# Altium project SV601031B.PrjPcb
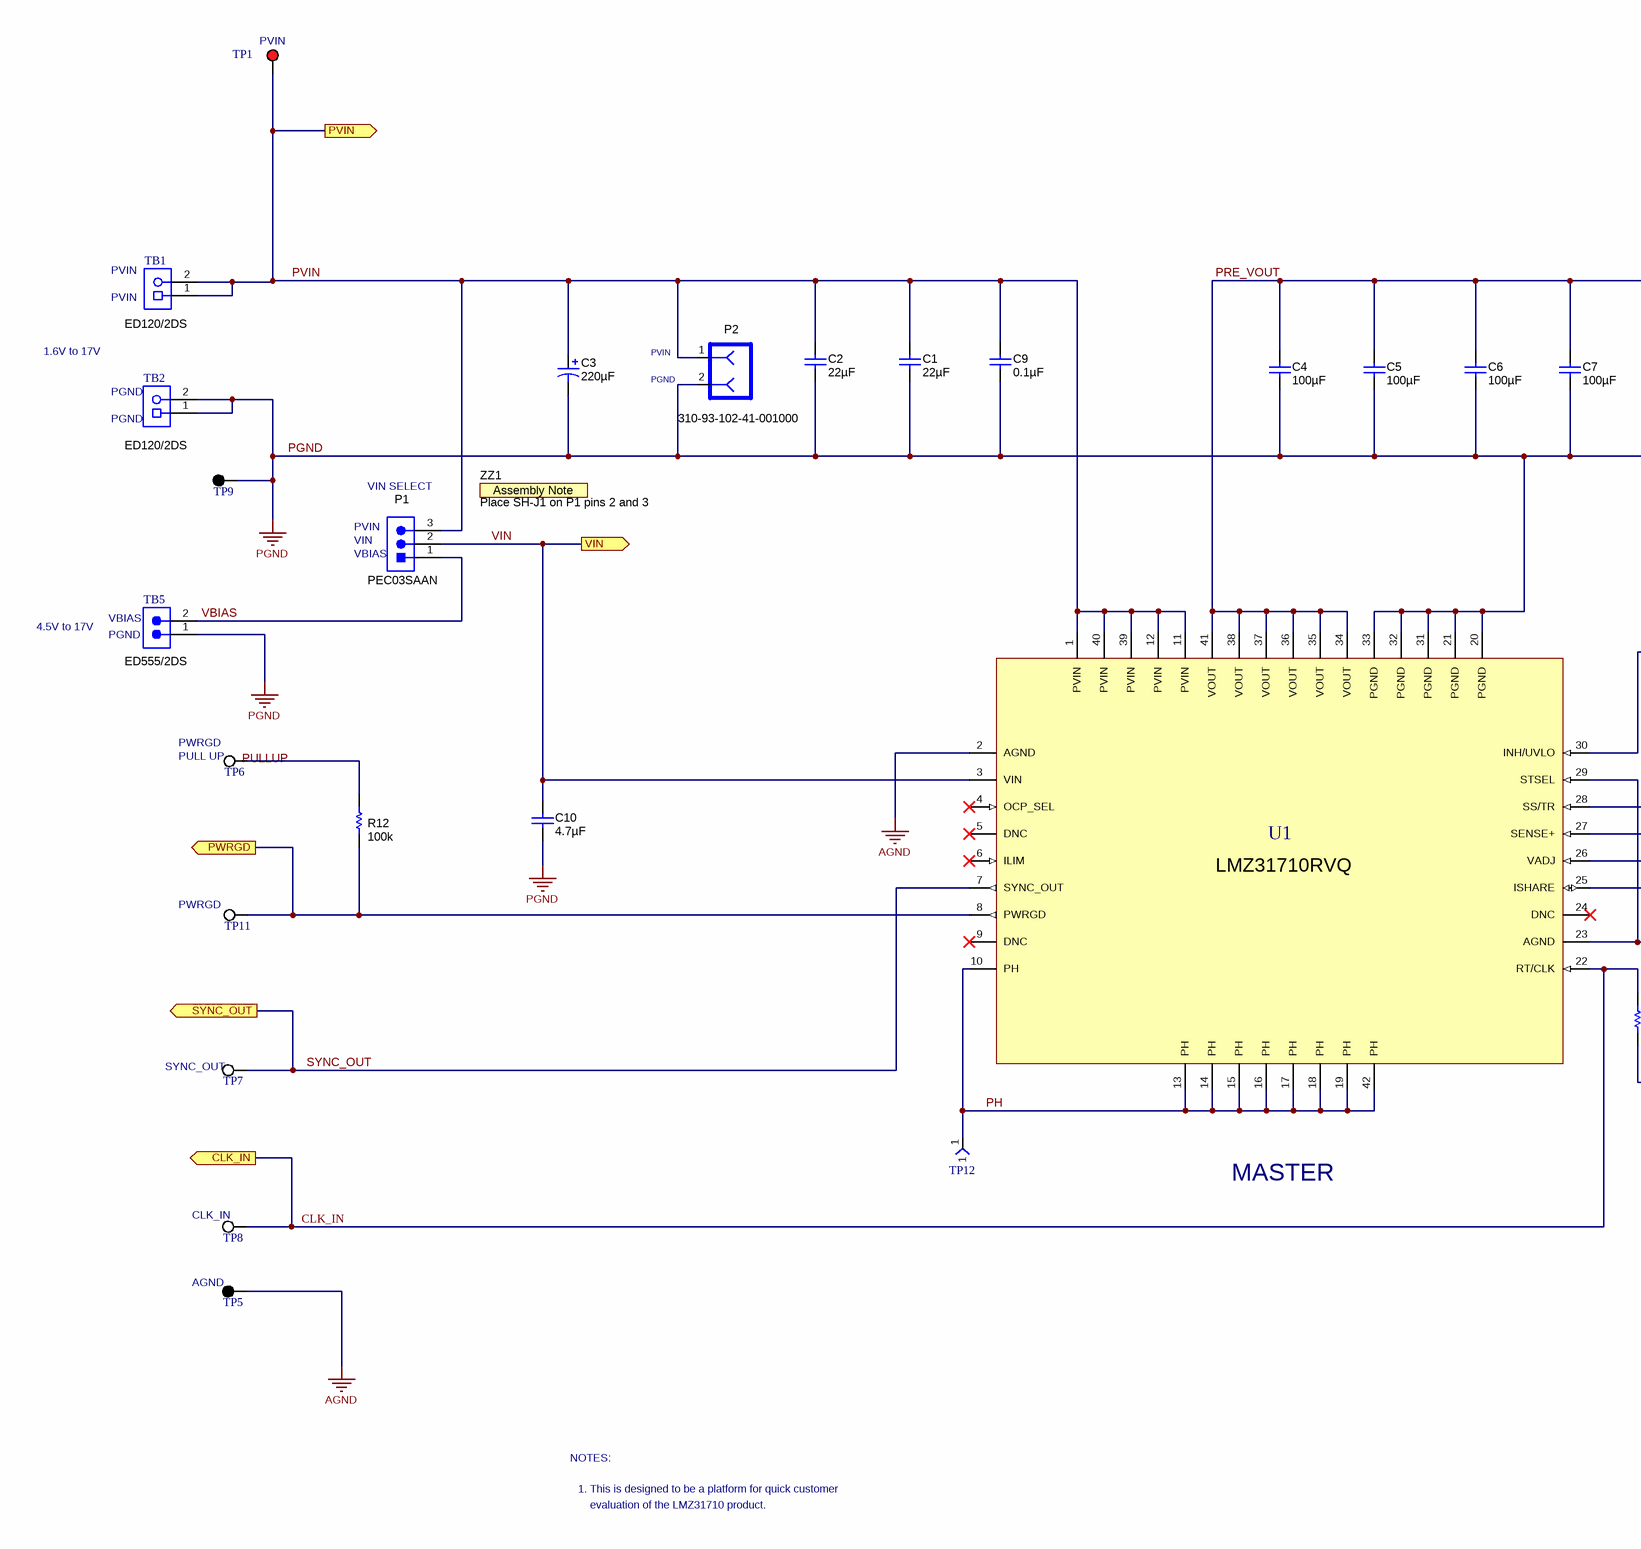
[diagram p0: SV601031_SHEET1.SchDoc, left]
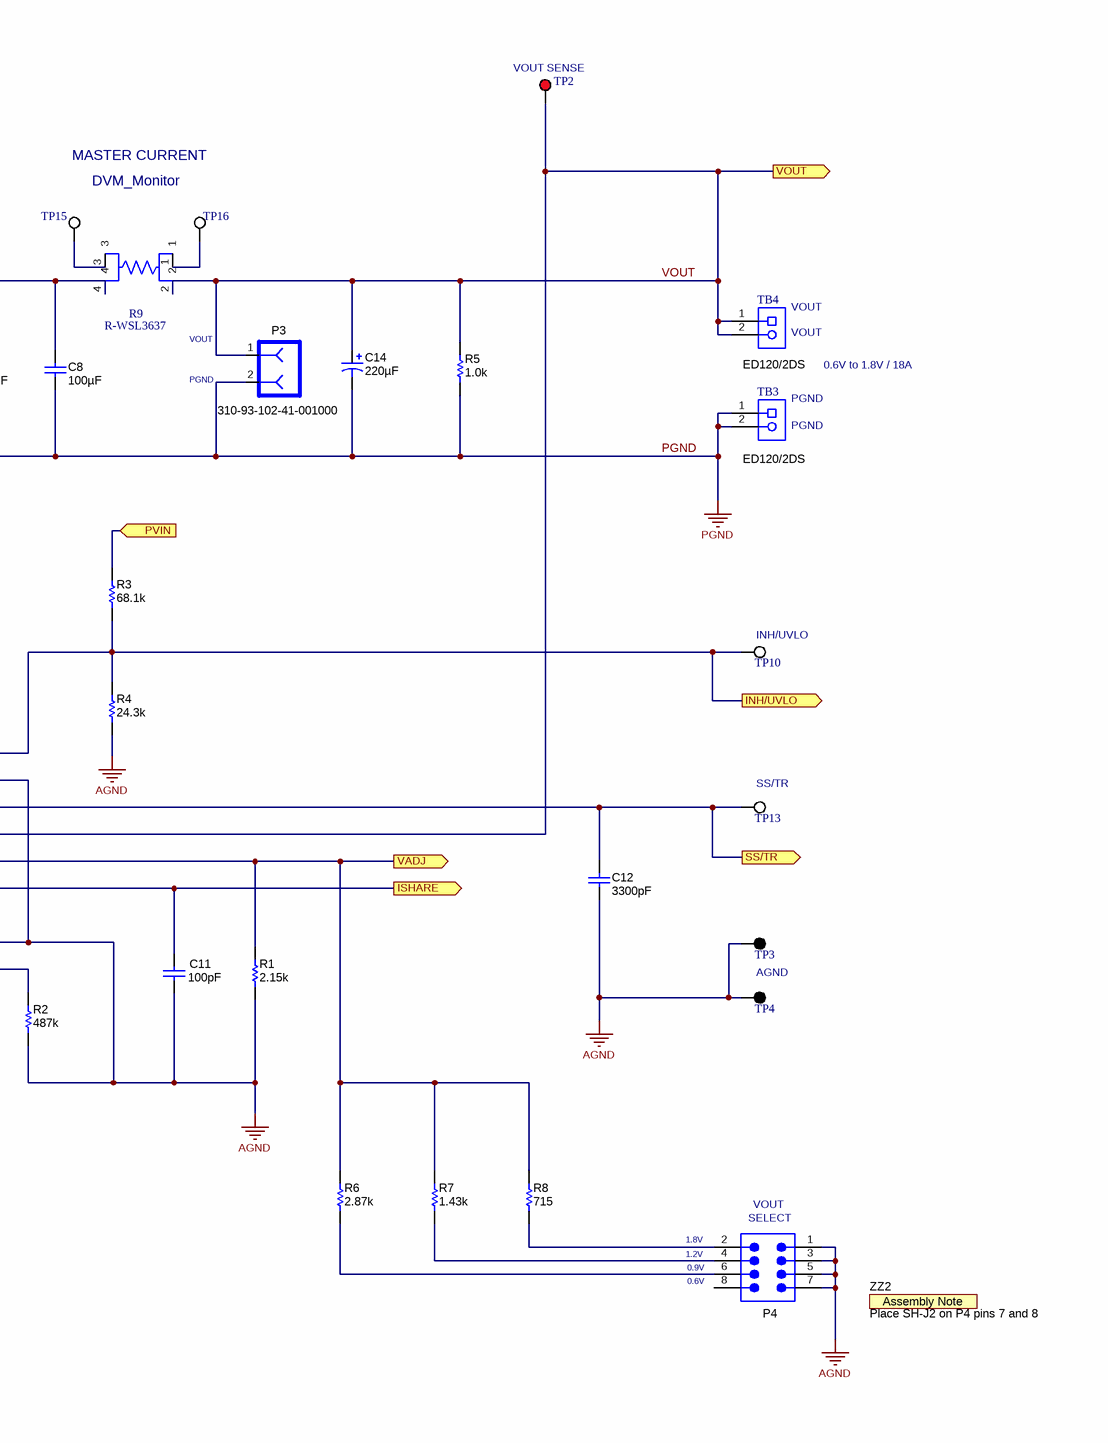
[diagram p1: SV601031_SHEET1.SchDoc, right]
CopyrightYear: 2013; PCB_Layout: James McTeague; PCB_Rev: A; PRJ_Customer: Public Release; PRJ_Engineer: Jason Arrigo; PRJ_Number: SV601031; PRJ_Title: LMZ31710X2EVM; SCH_Rev: A; TechSupport: http://www.ti.com/support
2 sheets, 82 parts. Net scope: flat (ports and power ports of the same name join across sheets).
Board file: SV601031A.PcbDoc
Sheets:
  SV601031_SHEET1.SchDoc
  SV601031_SHEET2.SchDoc

## Sheet SV601031_SHEET1.SchDoc: LMZ31710 2x Parallel  Board
size 558 x 431 mm; Engineer: Jason Arrigo; Revision: B; DRAWING NO: 89-01136; REV: 1A; File Name: 89-01136-1A.SCH; Number: 89-01136-1A; Name: Jason Arrigo; PageSetup: Record=PageOptions|CenterHorizontal=True|CenterVertical=True|PrintScale=1.00|XCorrection=1.00|YCorrection=1.00|PrintKind=0|BorderSize=5000000|LeftOffset=0|BottomOffset=0|Orientation=2|PaperLength=1000|PaperWidth=1000|Scale=100|PaperSource=15|PrintQuality=600|MediaType=1|DitherType=10|PaperKind=Letter|PrintScaleMode=1

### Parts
C1  ValueDisplayed: 22µF  [1210]  (hidden comment: 12103D226MAT2A)
C2  ValueDisplayed: 22µF  [1210]  (hidden comment: 12103D226MAT2A)
C3  ValueDisplayed: 220µF  [SM_RADIAL_G]  (hidden comment: EEE-FC1E221P)
C4  ValueDisplayed: 100µF  [1210]  (hidden comment: GRM32EC80J107ME20L)
C5  ValueDisplayed: 100µF  [1210]  (hidden comment: GRM32EC80J107ME20L)
C6  ValueDisplayed: 100µF  [1210]  (hidden comment: GRM32EC80J107ME20L)
C7  ValueDisplayed: 100µF  [1210]  (hidden comment: GRM32EC80J107ME20L)
C8  ValueDisplayed: 100µF  [1210]  (hidden comment: GRM32EC80J107ME20L)
C9  ValueDisplayed: 0.1µF  [0805_HV]  (hidden comment: C0805C104K3RACTU)
C10  ValueDisplayed: 4.7µF  [0603]  (hidden comment: GRM188R60J475KE19D)
C11  ValueDisplayed: 100pF  [0805]  (hidden comment: GRM2165C2A101JA01D)
C12  ValueDisplayed: 3300pF  [0805]  (hidden comment: C0805C332K5RACTU)
C14  ValueDisplayed: 220µF  [TPB_D4]  (hidden comment: 10TPB220M)
P1  PEC03SAAN  [CONN_PEC03SAAN]
P2  310-93-102-41-001000  [HDR100_1X2]
P3  310-93-102-41-001000  [HDR100_1X2]
P4  PEC04DAAN  [CONN_PEC04DAAN]  (value not drawn)
R1  value 2.15k  [0402]  (hidden comment: CRCW04022K15FKED)
R2  value 487k  [0402]  (hidden comment: CRCW0402487KFKED)
R3  value 68.1k  [0402]  (hidden comment: CRCW040268K1FKED)
R4  value 24.3k  [0402]  (hidden comment: CRCW040224K3FKED)
R5  value 1.0k  [0805_HV]  (hidden comment: ERJ-6GEYJ102V)
R6  value 2.87k  [0603]  (hidden comment: CRCW06032K87FKEA)
R7  value 1.43k  [0603]  (hidden comment: CRCW06031K43FKEA)
R8  value 715  [0603]  (hidden comment: CRCW0603715RFKEA)
R9  R-WSL3637
R12  value 100k  [0603]  (hidden comment: CRCW0603100KJNEA)
TB1  ED120/2DS  [CONN_ED120-2DS]
TB2  ED120/2DS  [CONN_ED120-2DS]
TB3  ED120/2DS  [CONN_ED120-2DS]
TB4  ED120/2DS  [CONN_ED120-2DS]
TB5  ED555/2DS  [TERM_BLK_ED555-2DS]
TP1  5010  [Keystone5010]  (value not drawn)
TP2  5010  [Keystone5010]  (value not drawn)
TP3  5011  [Keystone5011]  (value not drawn)
TP4  5011  [Keystone5011]  (value not drawn)
TP5  5011  [Keystone5011]  (value not drawn)
TP6  5012  [Keystone5012]  (value not drawn)
TP7  5012  [Keystone5012]  (value not drawn)
TP8  5012  [Keystone5012]  (value not drawn)
TP9  5011  [Keystone5011]  (value not drawn)
TP10  5012  [Keystone5012]  (value not drawn)
TP11  5012  [Keystone5012]  (value not drawn)
TP12  Comment  (value not drawn)
TP13  5012  [Keystone5012]  (value not drawn)
TP15  5012  [Keystone5012]  (value not drawn)
TP16  5012  [Keystone5012]  (value not drawn)
U1  LMZ31710RVQ  [RVQ0042A]
ZZ1  Place SH-J1 on P1 pins 2 and 3  [AssemblyNote]  (no BOM)
ZZ2  Place SH-J2 on P4 pins 7 and 8  [AssemblyNote]  (no BOM)

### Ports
CLK_IN, INH/UVLO, ISHARE, PVIN, PWRGD, SS/TR, SYNC_OUT, VADJ, VIN, VOUT

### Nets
AGND: C11.2 C12.2 P4.1 P4.3 P4.5 P4.7 R1.1 R2.1 R4.1 TP3.1 TP4.1 TP5.1 U1.2(AGND) U1.23(AGND) U1.29(STSEL)
PGND: C1.2 C2.2 C3.2(-) C4.2 C5.2 C6.2 C7.2 C8.2 C9.2 C10.2 C14.2(-) P2.2 P3.2 R5.2 TB2.1 TB2.2 TB3.1 TB3.2 TB5.1 TP9.1 U1.20(PGND) U1.21(PGND) U1.31(PGND) U1.32(PGND) U1.33(PGND)
CLK_IN: R2.2 TP8.1 U1.22(RT/CLK) ; port CLK_IN
INH/UVLO: R3.1 R4.2 TP10.1 U1.30(INH/UVLO) ; port INH/UVLO
ISHARE: C11.1 U1.25(ISHARE) ; port ISHARE
PH: TP12.1 U1.10(PH) U1.13(PH) U1.14(PH) U1.15(PH) U1.16(PH) U1.17(PH) U1.18(PH) U1.19(PH) U1.42(PH)
PRE_VOUT: C4.1 C5.1 C6.1 C7.1 C8.1 R9.4 U1.34(VOUT) U1.35(VOUT) U1.36(VOUT) U1.37(VOUT) U1.38(VOUT) U1.41(VOUT)
PVIN: C1.1 C2.1 C3.1(+) C9.1 P1.3 P2.1 R3.2 TB1.1 TB1.2 TP1.1 U1.1(PVIN) U1.11(PVIN) U1.12(PVIN) U1.39(PVIN) U1.40(PVIN) ; port PVIN
PWRGD: R12.1 TP11.1 U1.8(PWRGD) ; port PWRGD
SS/TR: C12.1 TP13.1 U1.28(SS/TR) ; port SS/TR
SYNC_OUT: TP7.1 U1.7(SYNC_OUT) ; port SYNC_OUT
VADJ: R1.2 R6.2 R7.2 R8.2 U1.26(VADJ) ; port VADJ
VBIAS: P1.1 TB5.2
VIN: C10.1 P1.2 U1.3(VIN) ; port VIN
VOUT: C14.1(+) P3.1 R5.1 R9.2 TB4.1 TB4.2 TP2.1 U1.27(SENSE+) ; port VOUT
NetP4_2: P4.2 R8.1
NetP4_4: P4.4 R7.1
NetP4_6: P4.6 R6.1
NetR9_1: R9.1 TP16.1
NetR9_3: R9.3 TP15.1
NetR12_2: R12.2 TP6.1

Not connected (* = marked no-connect by the designer): P4 8; U1 4(OCP_SEL)* 5(DNC)* 6(ILIM)* 9(DNC)* 24(DNC)*

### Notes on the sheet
- (near TP1) PVIN
- (near TP2) VOUT SENSE
- MASTER CURRENT
- DVM_Monitor
- (near TB1) PVIN
- (near TB4) VOUT
- 1.6V to 17V
- (near P2) PGND
- (near P2) PVIN
- VOUT
- (near P3) PGND
- 0.6V to 1.8V / 18A
- (near TB2) PGND
- (near TB3) PGND
- (near P1) VIN SELECT
- (near P1) VIN
- (near P1) PVIN
- (near P1) VBIAS
- 4.5V to 17V
- (near TB5) VBIAS
- (near TB5) PGND
- (near TP10) INH/UVLO
- (near TP6) PWRGD
- (near TP6) PULL UP
- (near TP13) SS/TR
- (near TP11) PWRGD
- AGND
- (near TP7) SYNC_OUT
- MASTER
- (near TP8) CLK_IN
- (near P4) 1.8V
- (near P4) 1.2V
- (near P4) SELECT
- (near P4) VOUT
- (near TP5) AGND
- (near P4) 0.9V
- (near P4) 0.6V
- NOTES:
- 1. This is designed to be a platform for quick customer
- evaluation of the LMZ31710 product.
- Labels drawn without touching a wire or pin: PULLUP

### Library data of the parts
C1 C2 = 12103D226MAT2A: CAP, CERM, 22uF, 25V, +/-20%, X5R, 1210; Manufacturer: AVX; Polarized: N; CompType: Capacitor; U/M: EA; Cap_F: 0.000022; Tolerance_%: 20; Value1: Unknown; VDC_V: 25; TaMin_C: -55; TaMax_C: 85
C3 = EEE-FC1E221P: CAP, AL, 220uF, 25V, +/-20%, 0.15 ohm, SMD; Manufacturer: Panasonic; Polarized: Y; CompType: Capacitor; U/M: EA; Cap_F: 0.00022; Tolerance_%: 20; VDC_V: 25; ESR_Ohm: 0.15; IRMS_A: 0.67; TaMin_C: -40; TaMax_C: 105; Cap_Case: G
C4-C8 = GRM32EC80J107ME20L: CAP, CERM, 100uF, 6.3V, +/-20%, X6S, 1210; Manufacturer: MuRata; Polarized: N; CompType: Capacitor; U/M: EA; Cap_F: 0.0001; Tolerance_%: 20; Value1: Unknown; VDC_V: 6.3; TaMin_C: -55; TaMax_C: 105
C9 = C0805C104K3RACTU: CAP, CERM, 0.1uF, 25V, +/-10%, X7R, 0805; Manufacturer: Kemet; Polarized: N; CompType: Capacitor; U/M: EA; Cap_F: 0.0000001; Tolerance_%: 10; ESR_Ohm: 0.064; Value1: 0.064 ohm; VDC_V: 25; IRMS_A: 1.64; TaMin_C: -55; TaMax_C: 125; Cap_Case: 0805
C10 = GRM188R60J475KE19D: CAP, CERM, 4.7uF, 6.3V, +/-10%, X5R, 0603; Manufacturer: MuRata; Polarized: N; CompType: Capacitor; U/M: EA; Cap_F: 0.0000047; Tolerance_%: 10; ESR_Ohm: 0.005; Value1: 0.005 ohm; VDC_V: 6.3; IRMS_A: 2; TaMin_C: -55; TaMax_C: 85
C11 = GRM2165C2A101JA01D: CAP, CERM, 100pF, 100V, +/-5%, C0G/NP0, 0805; Manufacturer: MuRata; Polarized: N; CompType: Capacitor; U/M: EA; Cap_F: 0.0000000001; Tolerance_%: 5; Value1: Unknown; VDC_V: 100; TaMin_C: -55; TaMax_C: 125
C12 = C0805C332K5RACTU: CAP, CERM, 3300pF, 50V, +/-10%, X7R, 0805; Manufacturer: Kemet; Polarized: N; CompType: Capacitor; U/M: EA; Cap_F: 0.0000000033; Tolerance_%: 10; ESR_Ohm: 0.332; Value1: 0.332 ohm; VDC_V: 50; IRMS_A: 0.319; TaMin_C: -55; TaMax_C: 125
C14 = 10TPB220M: CAP, TA, 220uF, 10V, +/-20%, 0.04 ohm, SMD; Manufacturer: Panasonic; Polarized: Y; CompType: Capacitor; U/M: EA; Cap_F: 0.00022; Tolerance_%: 20; VDC_V: 10; ESR_Ohm: 0.04; IRMS_A: 3; TaMin_C: -55; TaMax_C: 105; Cap_Case: D
P1 = PEC03SAAN: Header, 100mil, 3x1, Tin plated, TH; Manufacturer: Sullins Connector Solutions; SymbolCreator: a0799628; U/M: EA
P2 P3 = HEADER_310-93-102-41: Header, Female 2-pin, 100mil spacing,; Manufacturer: Mill-Max; Area: 20000
P4 = PEC04DAAN: Header, 100mil, 4x2, Tin plated, TH; Manufacturer: Sullins Connector Solutions; U/M: EA
R1 = CRCW04022K15FKED: RES, 2.15k ohm, 1%, 0.063W, 0402; Manufacturer: Vishay-Dale; CompType: Resistor; Res_ohm: 2150; Value_Code: 2k15; Tolerance_%: 1; Power_W: 0.063; VDC_V: 50; TempCo: 100 ppm/C; EIA_Code: E96; U/M: EA
R2 = CRCW0402487KFKED: RES, 487k ohm, 1%, 0.063W, 0402; Manufacturer: Vishay-Dale; CompType: Resistor; Res_ohm: 487000; Tolerance_%: 1; Power_W: 0.063; VDC_V: 50; TempCo: 100 ppm/C; EIA_Code: E96; U/M: EA
R3 = CRCW040268K1FKED: RES, 68.1k ohm, 1%, 0.063W, 0402; Manufacturer: Vishay-Dale; CompType: Resistor; Res_ohm: 68100; Value_Code: 68k1; Tolerance_%: 1; Power_W: 0.063; VDC_V: 50; TempCo: 100 ppm/C; EIA_Code: E96; U/M: EA
R4 = CRCW040224K3FKED: RES, 24.3k ohm, 1%, 0.063W, 0402; Manufacturer: Vishay-Dale; CompType: Resistor; Res_ohm: 24300; Value_Code: 24k3; Tolerance_%: 1; Power_W: 0.063; VDC_V: 50; TempCo: 100 ppm/C; EIA_Code: E96; U/M: EA
R5 = ERJ-6GEYJ102V: RES, 1.0k ohm, 5%, 0.125W, 0805; Manufacturer: Panasonic; CompType: Resistor; Res_ohm: 1000; Value_Code: 1k00; Tolerance_%: 5; Power_W: 0.125; VDC_V: 150; TempCo: 200 ppm/C; EIA_Code: E24; U/M: EA
R6 = CRCW06032K87FKEA: RES, 2.87k ohm, 1%, 0.1W, 0603; Manufacturer: Vishay-Dale; CompType: Resistor; Res_ohm: 2870; Value_Code: 2k87; Tolerance_%: 1; Power_W: 0.1; VDC_V: 75; TempCo: 100 ppm/C; EIA_Code: E96; U/M: EA
R7 = CRCW06031K43FKEA: RES, 1.43k ohm, 1%, 0.1W, 0603; Manufacturer: Vishay-Dale; CompType: Resistor; Res_ohm: 1430; Value_Code: 1k43; Tolerance_%: 1; Power_W: 0.1; VDC_V: 75; TempCo: 100 ppm/C; EIA_Code: E96; U/M: EA
R8 = CRCW0603715RFKEA: RES, 715 ohm, 1%, 0.1W, 0603; Manufacturer: Vishay-Dale; CompType: Resistor; Value_Code: 715R; Tolerance_%: 1; Power_W: 0.1; VDC_V: 75; TempCo: 100 ppm/C; EIA_Code: E96; U/M: EA
R9 = R-WSL3637: Current Sense Resistor,  SMD, 3W 0.001 ohm, 1%; MFR: Vishay Dale; PartNumber: WSL36371L000FEA; Manufacturer: Vishay-Dale; Second Source: C:\program files\p-cad 2004\pcad_pdf's\WSL3637.pdf; Reference: \\vette02\pmp_pcb\pcad_pdf's\WSL3637.pdf; Area: 184900; Value: 0.001
R12 = CRCW0603100KJNEA: RES, 100k ohm, 5%, 0.1W, 0603; Manufacturer: Vishay-Dale; CompType: Resistor; Res_ohm: 100000; Tolerance_%: 5; Power_W: 0.1; VDC_V: 75; TempCo: 200 ppm/C; EIA_Code: E24; U/M: EA
TB1-TB4 = ED120/2DS: TERMINAL BLOCK 5.08MM VERT 2POS, TH; Manufacturer: On-Shore Technology; SymbolCreator: a0412235; U/M: EA
TB5 = ED555/2DS: Terminal Block, 6A, 3.5mm Pitch, 2-Pos, TH; Manufacturer: On-Shore Technology; SymbolCreator: a0412235; CompType: Connector; U/M: EA
TP1 TP2 = 5010: Test Point, Multipurpose, Red, TH; Manufacturer: Keystone; CompType: Test Point Loop; U/M: EA
TP3-TP5 TP9 = 5011: Test Point, Multipurpose, Black, TH; Manufacturer: Keystone; CompType: Test Point Loop; U/M: EA
TP6-TP8 TP10 TP11 TP13 TP15 TP16 = 5012: Test Point, Multipurpose, White, TH; Manufacturer: Keystone; CompType: Test Point Loop; U/M: EA
TP12 = TP-038: Test Point, O.038 Hole; MFR: STD; Reference: \\vette02\pmp_pcb\pcad_pdf's\Keystone-SMT-TH_Test point.pdf; Second Source: C:\program files\p-cad 2004\pcad_pdf's\Keystone-SMT-TH_Test point.pdf; Value: STD
U1 = LMZ31710RVQ: 10A SIMPLE SWITCHER Power Module with 2.95V-17V Input and Current Sharing in QFN Package, RVQ0042A; Manufacturer: Texas Instruments; Alternate Manufacturer: None; SymbolCreator: a0411947; CompType: IC; U/M: EA
ZZ1 ZZ2 = AssemblyNote: This Assembly Note will show in the PcbDoc and associated outputs; SymbolCreator: codlsc

## Sheet SV601031_SHEET2.SchDoc: LMZ31710 2x Parallel  Board
size 558 x 431 mm; Engineer: Jason Arrigo; Revision: B; DRAWING NO: 89-01094; REV: 1A; File Name: 89-00944-1A.SCH; Number: 89-01136-1B; Name: Jason Arrigo; PageSetup: Record=PageOptions|CenterHorizontal=True|CenterVertical=True|PrintScale=1.00|XCorrection=1.00|YCorrection=1.00|PrintKind=0|BorderSize=5000000|LeftOffset=0|BottomOffset=0|Orientation=2|PaperLength=1000|PaperWidth=1000|Scale=100|PaperSource=15|PrintQuality=600|MediaType=1|DitherType=10|PaperKind=Letter|PrintScaleMode=1
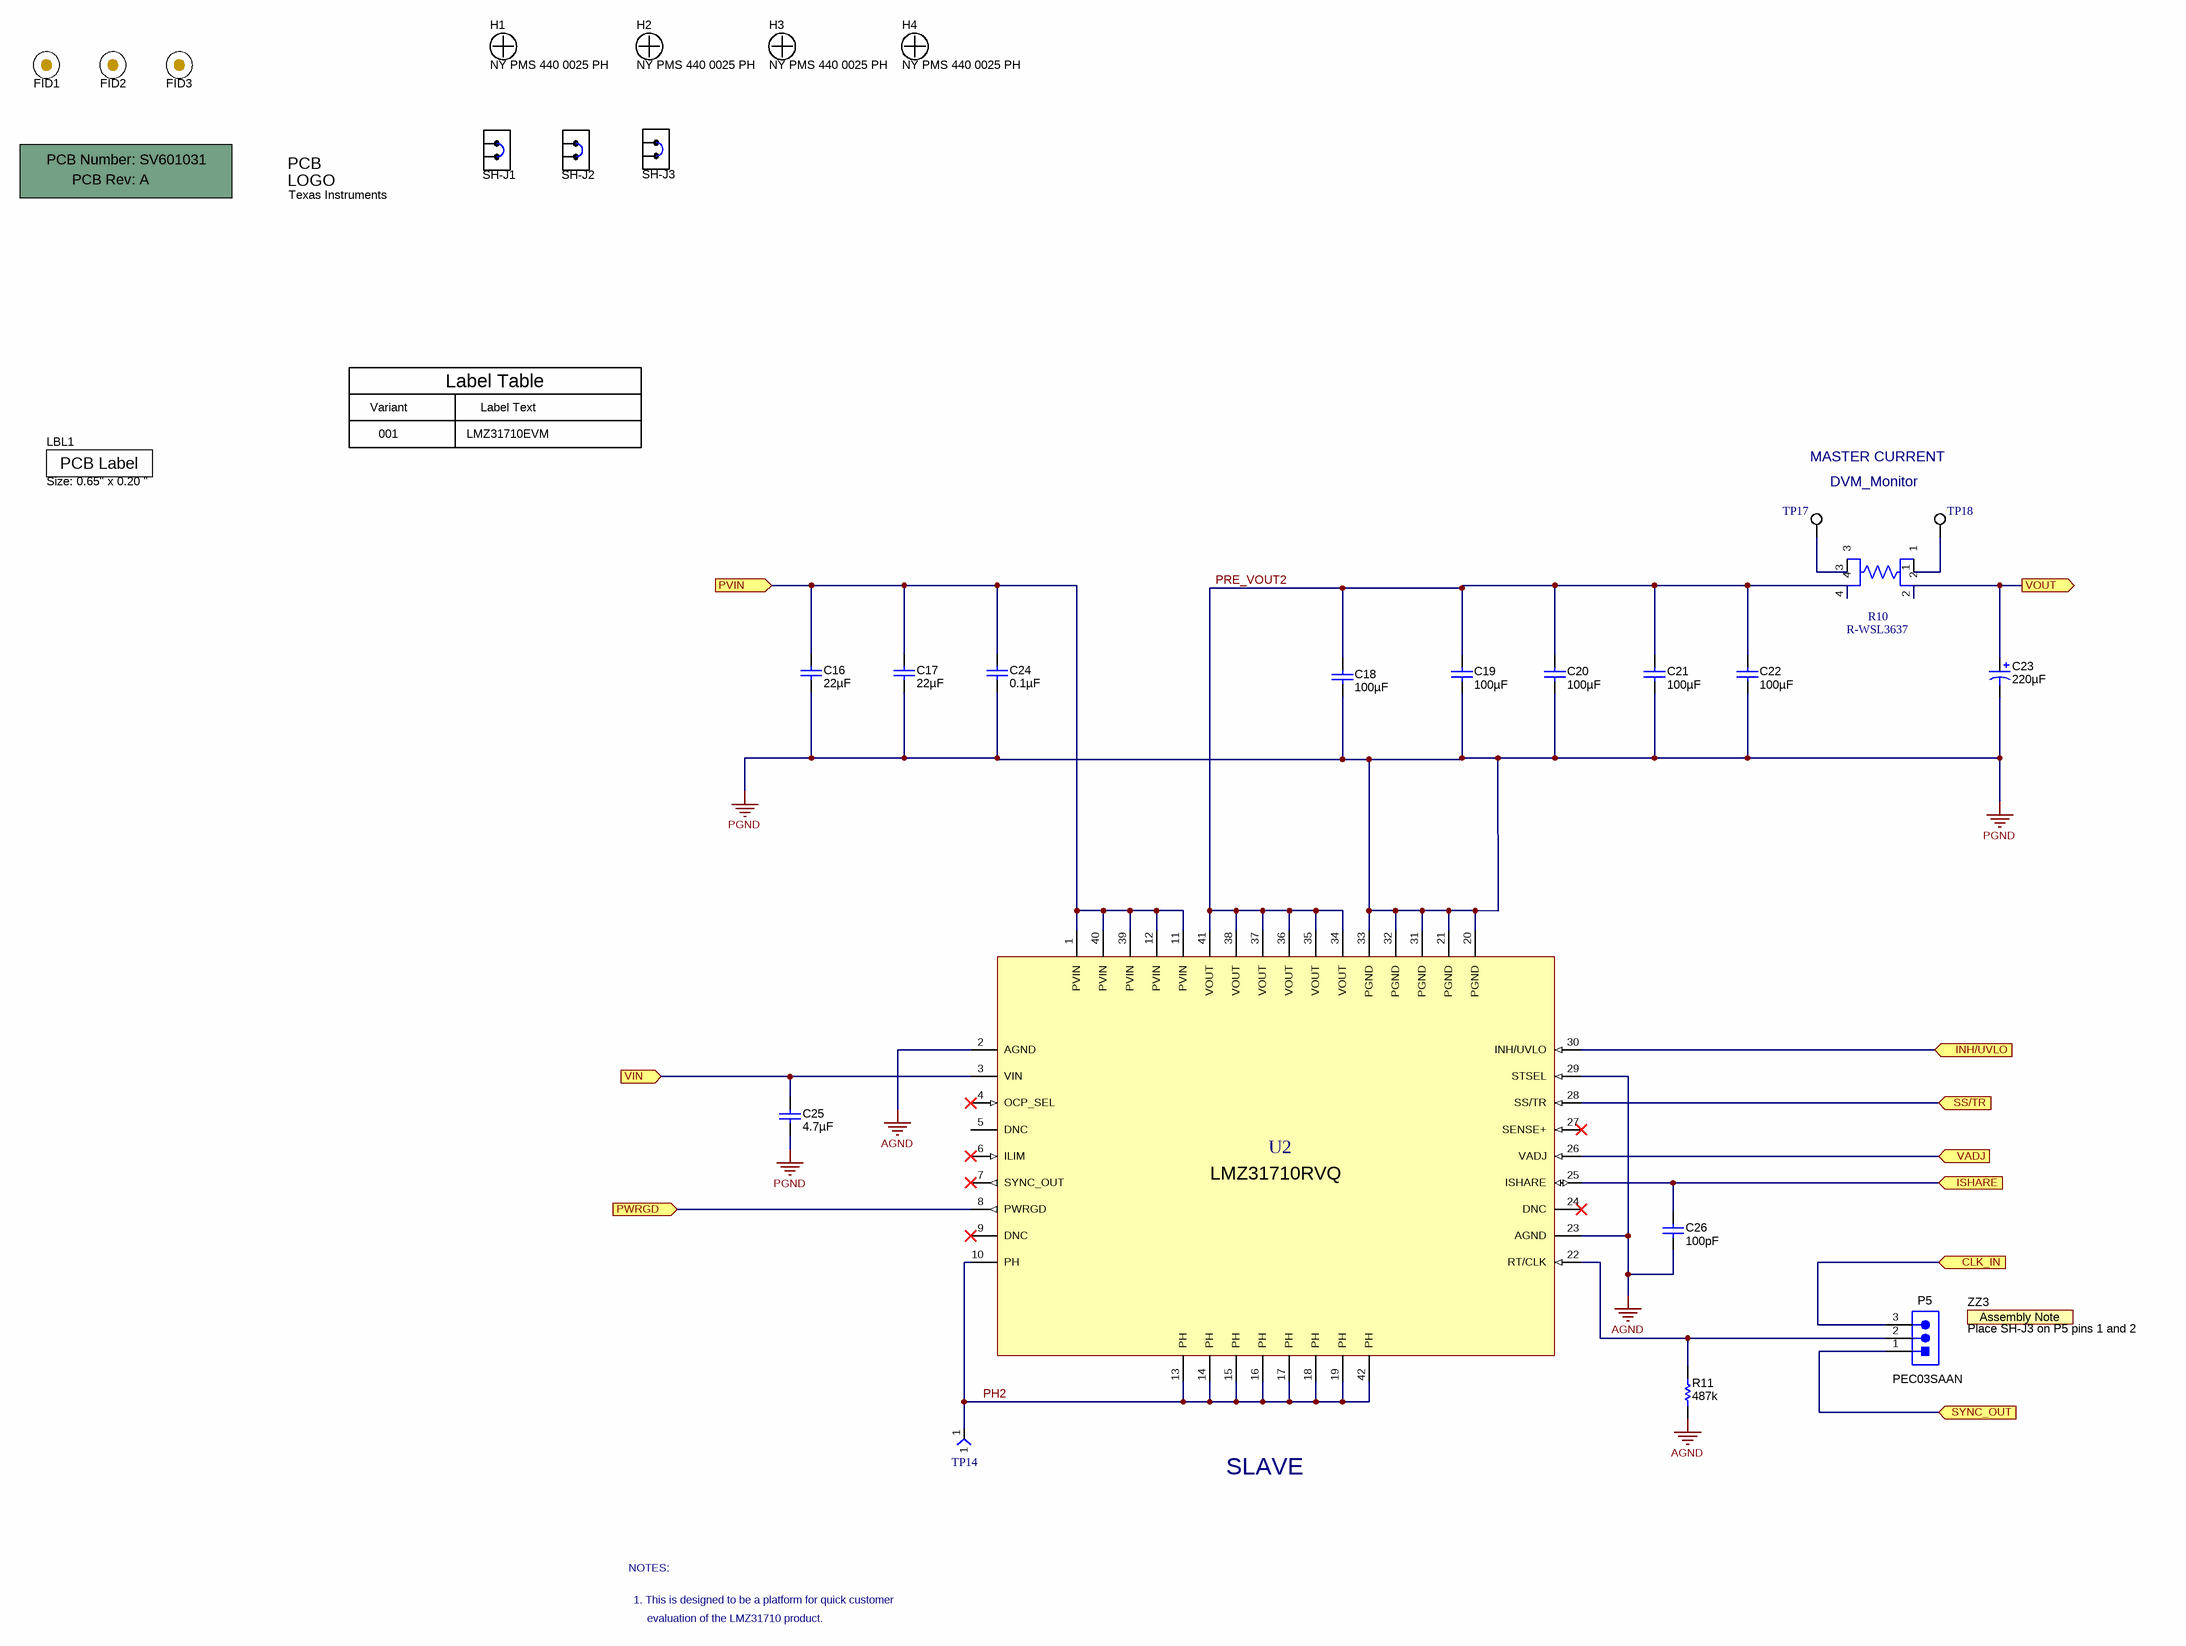
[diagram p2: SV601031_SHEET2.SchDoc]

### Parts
!PCB  Printed Circuit Board  (value not drawn)  (mechanical)
C16  ValueDisplayed: 22µF  [1210]  (hidden comment: 12103D226MAT2A)
C17  ValueDisplayed: 22µF  [1210]  (hidden comment: 12103D226MAT2A)
C18  ValueDisplayed: 100µF  [1210]  (hidden comment: GRM32EC80J107ME20L)
C19  ValueDisplayed: 100µF  [1210]  (hidden comment: GRM32EC80J107ME20L)
C20  ValueDisplayed: 100µF  [1210]  (hidden comment: GRM32EC80J107ME20L)
C21  ValueDisplayed: 100µF  [1210]  (hidden comment: GRM32EC80J107ME20L)
C22  ValueDisplayed: 100µF  [1210]  (hidden comment: GRM32EC80J107ME20L)
C23  ValueDisplayed: 220µF  [TPB_D4]  (hidden comment: 10TPB220M)
C24  ValueDisplayed: 0.1µF  [0805_HV]  (hidden comment: C0805C104K3RACTU)
C25  ValueDisplayed: 4.7µF  [0603]  (hidden comment: GRM188R60J475KE19D)
C26  ValueDisplayed: 100pF  [0805]  (hidden comment: GRM2165C2A101JA01D)
FID1  Fiducial  [Fiducial10-20]  (value not drawn)
FID2  Fiducial  [Fiducial10-20]  (value not drawn)
FID3  Fiducial  [Fiducial10-20]  (value not drawn)
H1  NY PMS 440 0025 PH  [NY PMS 440 0025 PH]
H2  NY PMS 440 0025 PH  [NY PMS 440 0025 PH]
H3  NY PMS 440 0025 PH  [NY PMS 440 0025 PH]
H4  NY PMS 440 0025 PH  [NY PMS 440 0025 PH]
LBL1  Size: 0.65" x 0.20 "  [Label_650x200]
Logo1  Texas Instruments  [TI_Stacked_Overlay_Small]  (no BOM)
P5  PEC03SAAN  [CONN_PEC03SAAN]
R10  R-WSL3637
R11  value 487k  [0402]  (hidden comment: CRCW0402487KFKED)
SH-J1  2SN-BK-G  [2SN-BK-G]  (value not drawn)
SH-J2  2SN-BK-G  [2SN-BK-G]  (value not drawn)
SH-J3  2SN-BK-G  [2SN-BK-G]  (value not drawn)
TP14  Comment  (value not drawn)
TP17  5012  [Keystone5012]  (value not drawn)
TP18  5012  [Keystone5012]  (value not drawn)
U2  LMZ31710RVQ  [RVQ0042A]
ZZ3  Place SH-J3 on P5 pins 1 and 2  [AssemblyNote]  (no BOM)

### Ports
CLK_IN, INH/UVLO, ISHARE, PVIN, PWRGD, SS/TR, SYNC_OUT, VADJ, VIN, VOUT

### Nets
AGND: C26.2 R11.1 U2.2(AGND) U2.23(AGND) U2.29(STSEL)
PGND: C16.2 C17.2 C18.2 C19.2 C20.2 C21.2 C22.2 C23.2(-) C24.2 C25.2 U2.20(PGND) U2.21(PGND) U2.31(PGND) U2.32(PGND) U2.33(PGND)
CLK_IN: P5.3 ; port CLK_IN
INH/UVLO: U2.30(INH/UVLO) ; port INH/UVLO
ISHARE: C26.1 U2.25(ISHARE) ; port ISHARE
PH2: TP14.1 U2.10(PH) U2.13(PH) U2.14(PH) U2.15(PH) U2.16(PH) U2.17(PH) U2.18(PH) U2.19(PH) U2.42(PH)
PRE_VOUT2: C18.1 C19.1 C20.1 C21.1 C22.1 R10.4 U2.34(VOUT) U2.35(VOUT) U2.36(VOUT) U2.37(VOUT) U2.38(VOUT) U2.41(VOUT)
PVIN: C16.1 C17.1 C24.1 U2.1(PVIN) U2.11(PVIN) U2.12(PVIN) U2.39(PVIN) U2.40(PVIN) ; port PVIN
PWRGD: U2.8(PWRGD) ; port PWRGD
SS/TR: U2.28(SS/TR) ; port SS/TR
SYNC_OUT: P5.1 ; port SYNC_OUT
VADJ: U2.26(VADJ) ; port VADJ
VIN: C25.1 U2.3(VIN) ; port VIN
VOUT: C23.1(+) R10.2 ; port VOUT
NetP5_2: P5.2 R11.2 U2.22(RT/CLK)
NetR10_1: R10.1 TP18.1
NetR10_3: R10.3 TP17.1

Not connected (* = marked no-connect by the designer): U2 4(OCP_SEL)* 5(DNC) 6(ILIM)* 7(SYNC_OUT)* 9(DNC)* 24(DNC)* 27(SENSE+)*

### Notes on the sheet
- Label Table
- Variant
- 001
- Label Text
- LMZ31710EVM
- MASTER CURRENT
- DVM_Monitor
- SLAVE
- NOTES:
- 1. This is designed to be a platform for quick customer
- evaluation of the LMZ31710 product.

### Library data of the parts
!PCB = PCB: Manufacturer: Any; PartNumber: SV601031; SymbolCreator: a0412235
C16 C17 = 12103D226MAT2A: as C1 on sheet SV601031_SHEET1
C18-C22 = GRM32EC80J107ME20L: as C4 on sheet SV601031_SHEET1
C23 = 10TPB220M: as C14 on sheet SV601031_SHEET1
C24 = C0805C104K3RACTU: as C9 on sheet SV601031_SHEET1
C25 = GRM188R60J475KE19D: as C10 on sheet SV601031_SHEET1
C26 = GRM2165C2A101JA01D: as C11 on sheet SV601031_SHEET1
FID1-FID3 = Fiducial: Fiducial mark.  There is nothing to buy or mount.; SymbolCreator: codlsc
H1-H4 = NY PMS 440 0025 PH: Machine Screw, Round, #4-40 x 1/4, Nylon, Philips panhead; Manufacturer: B&F Fastener Supply; CompType: Hardware; SymbolCreator: codlsc; U/M: EA
LBL1 = THT-14-423-10: Thermal Transfer Printable Labels, 0.650" W x 0.200" H - 10,000 per roll; Manufacturer: Brady; SymbolCreator: a0412235; CompType: Label
Logo1 = TI_Logo: Texas Instrument Corporate Signature; SymbolCreator: codlsc
P5 = PEC03SAAN: as P1 on sheet SV601031_SHEET1
R10 = R-WSL3637: as R9 on sheet SV601031_SHEET1
R11 = CRCW0402487KFKED: as R2 on sheet SV601031_SHEET1
SH-J1-SH-J3 = 2SN-BK-G: Shunt, 2mm, Gold plated, Black; Manufacturer: Samtec; Value: 1x2; Note: You can "mate" this to a header by matching the designator.  i.e. use SH-J3 for header J3
TP14 = TP-038: as TP12 on sheet SV601031_SHEET1
TP17 TP18 = 5012: as TP6 on sheet SV601031_SHEET1
U2 = LMZ31710RVQ: as U1 on sheet SV601031_SHEET1
ZZ3 = AssemblyNote: as ZZ1 on sheet SV601031_SHEET1

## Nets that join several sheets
AGND: SV601031_SHEET1 (15 pins), SV601031_SHEET2 (5 pins)
PGND: SV601031_SHEET1 (25 pins), SV601031_SHEET2 (15 pins)
CLK_IN: SV601031_SHEET1 (R2.2 TP8.1 U1.22), SV601031_SHEET2 (P5.3)
INH/UVLO: SV601031_SHEET1 (R3.1 R4.2 TP10.1 U1.30), SV601031_SHEET2 (U2.30)
ISHARE: SV601031_SHEET1 (C11.1 U1.25), SV601031_SHEET2 (C26.1 U2.25)
PVIN: SV601031_SHEET1 (15 pins), SV601031_SHEET2 (8 pins)
PWRGD: SV601031_SHEET1 (R12.1 TP11.1 U1.8), SV601031_SHEET2 (U2.8)
SS/TR: SV601031_SHEET1 (C12.1 TP13.1 U1.28), SV601031_SHEET2 (U2.28)
SYNC_OUT: SV601031_SHEET1 (TP7.1 U1.7), SV601031_SHEET2 (P5.1)
VADJ: SV601031_SHEET1 (5 pins), SV601031_SHEET2 (U2.26)
VIN: SV601031_SHEET1 (C10.1 P1.2 U1.3), SV601031_SHEET2 (C25.1 U2.3)
VOUT: SV601031_SHEET1 (8 pins), SV601031_SHEET2 (C23.1 R10.2)

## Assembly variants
001: not fitted C11 C12 C26 H1 H2 H3 H4 LBL1 R1 R5 TP12 TP14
